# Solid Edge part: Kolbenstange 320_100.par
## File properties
Username: ahadarics
Dokumentum tartalom típus: 0
Author: ahadarics
Last saved by: ahadarics
Revision: 81
Sűrűség: 0,000 kg/m^3
Pontosság: 0,990
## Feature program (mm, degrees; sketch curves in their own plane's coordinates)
base feature "unnamed BaseFeature 1"
thread "unnamed Thread 1"
chamfer "Letörés_1"  SetBackValue2 = 20 deg
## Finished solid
Body 1: solid body, 19 faces, 27 edges, 11 vertices.
  Faces by surface: plane 8, cylinder 5, cone 3, torus 3
  Edges by curve: circle 15, line 7, curve on surface 3, ellipse 2
Bounding box of the edges (mm; curved faces can reach further): 320.000 x 320.000 x 471.000, from (-160, -160, -223) to (160, 160, 248).
Cylindrical faces by radius (mm): R22.4 x1, R24 x1, R31 x1, R31.5 x1, R160 x1
Conical faces (half-angle, radius in mm at the cone's reference point): 20 deg R24 x1, 30 deg R31.25 x1, 60 deg R23.2 x1
Toroidal faces (ring radius, tube radius in mm): R23.2 r0.8 x2, R25 r6 x1
Planar faces by outward normal: +x 1, +z 3, -x 1, -z 1, oblique 2
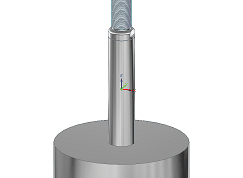
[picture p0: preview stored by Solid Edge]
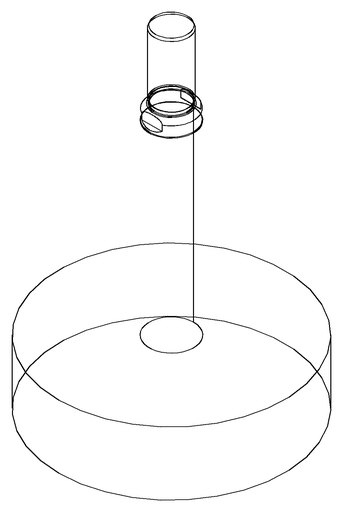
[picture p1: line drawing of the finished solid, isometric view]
